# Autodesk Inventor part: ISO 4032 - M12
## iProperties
Created: 2007-05
Part Number: ISO 4032 - M12
Material: Steel, Mild
Description: Hex Nut
Vendor: Autodesk Inc.
Document SubType Name: Modeling
Standard: ISO 4032
Designer: kurs1
Standards Organization: ISO
Language: en-US
Size Designation: M12
Categories: <MemberInstance Version="R10.0.0"><Categories><Category DisplayName="Fasteners" InternalName="e4da775c-781d-43d5-af7c-5136215cf5a6" Mnemonic="FSTN"><Category Di
Density: 1 g/cm^3
Author: kurs1
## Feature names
1. Body [Extrusion]
2. Chamfer1 [Revolution]
3. Thread [Hole]
4. Chamfer2
5. Chamfer3
